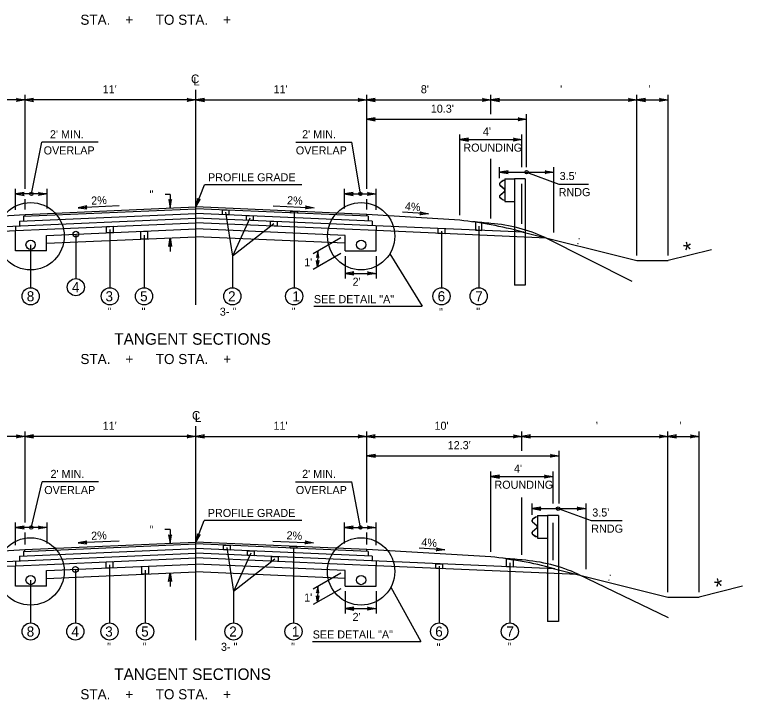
# Model space of a CAD drawing. Extents: x -540 to 1231, y -564 to 421.
# Drawn here: x -30 to 96.3, y 58.8 to 177.6 of the extents above; entities that cross this region are included whole.
import ezdxf

# ---------------------------------------------------------------- set-up
doc = ezdxf.new("R2010")
doc.units = 0
doc.layers.add('1', color=7, linetype='Continuous')
doc.layers.add('Des_ Drain_ Ftrs', color=7, linetype='Continuous')

msp = doc.modelspace()

# ---------------------------------------------------------------- linework, layer by layer
at = {"layer": '1'}
for p, q in [((1.44, 127.24), (1.44, 164.55)), ((-28.2, 147.36), (-28.2, 163.67)), ((31.07, 147.36), (31.07, 163.67)), ((52.63, 160.3), (52.63, 163.67)), ((77.95, 135.79), (77.95, 163.67)), ((83.34, 135.79), (83.34, 163.67)), ((-28.2, 162.79), (-49.75, 162.79)), ((1.44, 162.79), (-28.2, 162.79)), ((1.44, 162.79), (31.07, 162.79)), ((31.07, 162.79), (52.63, 162.79)), ((52.63, 162.79), (77.95, 162.79)), ((77.95, 162.79), (83.34, 162.79)), ((31.07, 159.42), (58.82, 159.42)), ((58.82, 151.14), (58.82, 160.3)), ((47.24, 142.79), (47.24, 156.79)), ((58.01, 151.14), (58.01, 156.79)), ((-27.1, 146.48), (-25.3, 155.43)), ((-15.54, 155.43), (-25.3, 155.43)), ((18.75, 155.43), (28.51, 155.43)), ((29.97, 146.48), (28.51, 155.43)), ((47.24, 155.91), (58.01, 155.91)), ((52.63, 142.23), (52.63, 152.58)), ((54.13, 149.19), (54.13, 151.14)), ((54.13, 150.26), (63.51, 150.26)), ((58.82, 150.26), (64.38, 148.19)), ((63.51, 139.78), (63.51, 151.14)), ((55.04, 149.08), (55.04, 145.15)), ((55.04, 149.08), (56.73, 149.08)), ((56.73, 149.08), (56.73, 130.68)), ((58.55, 149.08), (56.73, 149.08)), ((58.55, 149.08), (58.55, 130.68)), ((1.44, 144.22), (2.92, 148.08)), ((19.84, 148.08), (2.92, 148.08)), ((54.2, 147.97), (54.93, 147.34)), ((54.73, 148.79), (54.21, 148.41)), ((54.22, 148), (54.95, 147.36)), ((54.74, 148.77), (54.23, 148.38)), ((55.04, 148.85), (54.73, 148.79)), ((55.04, 148.82), (54.74, 148.77)), ((58.01, 141.27), (58.01, 148.22)), ((64.38, 148.19), (69.53, 148.19)), ((-29.84, 143.7), (-29.84, 147.36)), ((-24.35, 146.48), (-29.84, 146.48)), ((-24.35, 143.97), (-24.35, 147.36)), ((27.23, 143.97), (27.23, 147.36)), ((27.23, 146.48), (32.71, 146.48)), ((32.71, 143.7), (32.71, 147.36)), ((54.93, 146.89), (54.2, 146.25)), ((54.95, 146.86), (54.22, 146.23)), ((55.01, 147.15), (55.01, 147.07)), ((55.04, 147.15), (55.04, 147.07)), ((-28.2, 143.8), (-28.2, 145.6)), ((-3.02, 146.39), (-3.9, 146.39)), ((-3.02, 146.39), (-3.02, 144.02)), ((31.07, 143.8), (31.07, 145.6)), ((54.21, 145.82), (54.73, 145.43)), ((54.23, 145.84), (54.74, 145.46)), ((54.73, 145.43), (55.04, 145.37)), ((54.74, 145.46), (55.04, 145.4)), ((-28.2, 142.92), (1.44, 144.22)), ((-11.88, 144.4), (-18.97, 144.09)), ((31.08, 142.92), (1.44, 144.22)), ((14.87, 144.39), (21.95, 144.08)), ((55.04, 145.15), (56.73, 145.15)), ((-44.35, 141.91), (-28.2, 142.92)), ((-29.14, 141.77), (1.44, 143.11)), ((-28.44, 142.61), (1.44, 143.92)), ((-28.2, 142.62), (-28.2, 142.92)), ((31.31, 142.61), (1.44, 143.92)), ((32.02, 141.77), (1.44, 143.11)), ((6.6, 143.29), (7.77, 135.66)), ((18.48, 143.31), (18.48, 130.21)), ((31.08, 142.62), (31.08, 142.92)), ((47.24, 141.91), (31.08, 142.92)), ((41.79, 143.01), (37.3, 143.29)), ((-55.46, 139.82), (1.44, 142.3)), ((-29.14, 141.75), (-29.14, 140.97)), ((-28.44, 142.6), (-28.44, 141.8)), ((-24.36, 140.36), (1.44, 141.49)), ((58.35, 139.82), (1.44, 142.3)), ((27.23, 140.36), (1.44, 141.49)), ((10.78, 142.3), (7.77, 135.66)), ((31.31, 142.61), (31.31, 141.8)), ((32.02, 141.77), (32.02, 140.96)), ((-29.85, 140.94), (-29.85, 140.13)), ((-29.85, 140.13), (-24.36, 140.36)), ((-24.46, 139.28), (1.44, 140.41)), ((-13.48, 140.3), (-13.48, 130.21)), ((27.33, 139.28), (1.44, 140.41)), ((14.96, 141.29), (7.77, 135.66)), ((32.72, 140.13), (27.23, 140.36)), ((32.72, 140.93), (32.72, 140.13)), ((50.5, 140.86), (50.5, 130.21)), ((54.13, 141.13), (54.13, 141.13)), ((-59.39, 138.83), (-29.85, 140.13)), ((-29.85, 136.59), (-29.85, 140.13)), ((-24.46, 136.59), (-24.46, 139.28)), ((-24.46, 137.93), (1.44, 139.06)), ((-19.39, 139.5), (-19.39, 131.79)), ((-7.55, 139.35), (-7.55, 130.21)), ((27.33, 137.93), (1.44, 139.06)), ((27.33, 136.59), (27.33, 139.28)), ((27.33, 139.28), (27.33, 139.28)), ((32.72, 136.59), (32.72, 140.13)), ((62.27, 138.83), (32.72, 140.13)), ((44.04, 140.04), (44.04, 130.21)), ((58.01, 139.9), (77.95, 134.91)), ((62.01, 138.9), (77.07, 131.37)), ((-27.23, 137.66), (-27.23, 130.21)), ((-3.02, 138.87), (-3.02, 136.5)), ((26.57, 138.84), (21.81, 136.09)), ((-24.46, 136.59), (-29.85, 136.59)), ((22.57, 136.53), (22.55, 133.83)), ((27.33, 136.59), (32.72, 136.59)), ((90.88, 136.8), (83.34, 134.91)), ((90.88, 136.8), (83.34, 134.91)), ((7.77, 135.66), (7.77, 130.21)), ((26.57, 136.15), (21.8, 133.39)), ((27.33, 135.71), (27.33, 131.82)), ((32.72, 135.71), (32.72, 131.82)), ((35.09, 136.1), (40.68, 127.02)), ((77.95, 134.91), (83.34, 134.91)), ((27.33, 132.7), (32.72, 132.7)), ((58.55, 130.68), (56.73, 130.68)), ((21.9, 127.02), (40.68, 127.02)), ((1.43, 69.09), (1.43, 106.18)), ((-28.2, 89.51), (-28.2, 105.3)), ((31.07, 89.51), (31.07, 105.3)), ((58.01, 101.93), (58.01, 105.3)), ((83.33, 77.41), (83.33, 105.3)), ((88.72, 77.41), (88.72, 105.3)), ((-28.2, 104.42), (-55.14, 104.42)), ((1.43, 104.42), (-28.2, 104.42)), ((1.43, 104.42), (31.07, 104.42)), ((31.07, 104.42), (58.01, 104.42)), ((58.01, 104.42), (83.33, 104.42)), ((83.33, 104.42), (88.72, 104.42)), ((31.08, 101.05), (64.45, 101.05)), ((64.45, 92.78), (64.45, 101.93)), ((52.62, 84.41), (52.62, 98.32)), ((52.62, 97.44), (63.4, 97.44)), ((63.4, 92.78), (63.4, 98.32)), ((-27.08, 88.74), (-25.21, 96.52)), ((-15.44, 96.52), (-25.21, 96.52)), ((18.74, 96.52), (28.51, 96.52)), ((29.97, 88.63), (28.51, 96.52)), ((58.01, 83.87), (58.01, 93.8)), ((59.75, 90.82), (59.75, 92.78)), ((69.14, 81.41), (69.14, 92.78)), ((59.75, 91.9), (69.14, 91.9)), ((64.27, 91.9), (70.03, 89.82)), ((1.43, 86.07), (2.89, 89.85)), ((19.81, 89.85), (2.89, 89.85)), ((60.37, 90.43), (59.84, 90.04)), ((60.39, 90.4), (59.86, 90.01)), ((60.7, 90.48), (60.37, 90.43)), ((60.7, 90.45), (60.39, 90.4)), ((60.7, 90.71), (60.7, 86.78)), ((60.7, 90.71), (62.45, 90.71)), ((62.45, 90.71), (62.45, 72.31)), ((64.34, 90.71), (62.45, 90.71)), ((64.34, 90.71), (64.34, 72.31)), ((70.03, 89.82), (75.38, 89.82)), ((-24.38, 88.63), (-29.86, 88.63)), ((-29.84, 85.56), (-29.84, 89.51)), ((-24.36, 85.83), (-24.36, 89.51)), ((27.23, 85.83), (27.23, 89.51)), ((27.23, 88.63), (32.71, 88.63)), ((32.71, 85.56), (32.71, 89.51)), ((59.82, 89.61), (60.58, 88.97)), ((60.58, 88.52), (59.82, 87.88)), ((59.84, 89.63), (60.6, 88.99)), ((60.6, 88.5), (59.84, 87.86)), ((60.67, 88.78), (60.67, 88.71)), ((60.7, 88.78), (60.7, 88.71)), ((63.4, 82.95), (63.4, 89.42)), ((-28.2, 85.66), (-28.2, 87.75)), ((-3.05, 88.25), (-3.93, 88.25)), ((-3.05, 88.25), (-3.05, 85.88)), ((31.07, 85.66), (31.07, 87.75)), ((59.84, 87.45), (60.37, 87.06)), ((59.86, 87.48), (60.39, 87.09)), ((-28.21, 84.78), (1.43, 86.07)), ((-11.89, 86.27), (-18.97, 85.96)), ((31.07, 84.78), (1.43, 86.07)), ((14.78, 86.27), (21.86, 85.96)), ((60.37, 87.06), (60.7, 87.01)), ((60.39, 87.09), (60.7, 87.04)), ((60.7, 86.78), (62.45, 86.78)), ((-49.74, 83.53), (-28.21, 84.78)), ((-29.15, 83.63), (1.43, 84.96)), ((-28.44, 84.47), (1.43, 85.77)), ((-28.21, 84.48), (-28.21, 84.78)), ((31.31, 84.47), (1.43, 85.77)), ((32.02, 83.63), (1.43, 84.96)), ((6.81, 85.13), (7.97, 77.51)), ((18.38, 85.18), (18.38, 72.06)), ((31.07, 84.48), (31.07, 84.78)), ((52.62, 83.53), (31.07, 84.78)), ((44.64, 84.74), (40.15, 85.01)), ((-60.85, 81.44), (1.43, 84.16)), ((-29.14, 83.63), (-29.14, 82.82)), ((-28.44, 84.47), (-28.44, 83.66)), ((-24.36, 82.22), (1.43, 83.35)), ((63.72, 81.44), (1.43, 84.16)), ((27.23, 82.22), (1.43, 83.35)), ((10.98, 84.15), (7.97, 77.51)), ((31.31, 84.47), (31.31, 83.65)), ((32.02, 83.63), (32.02, 82.82)), ((-29.85, 82.79), (-29.85, 81.98)), ((-29.85, 81.98), (-24.36, 82.22)), ((-24.46, 81.14), (1.43, 82.27)), ((-13.54, 82.15), (-13.54, 72.06)), ((27.33, 81.14), (1.43, 82.27)), ((15.16, 83.14), (7.97, 77.51)), ((32.72, 81.98), (27.23, 82.22)), ((32.72, 82.79), (32.72, 81.98)), ((55.9, 82.47), (55.9, 72.06)), ((59.75, 82.76), (59.75, 82.76)), ((-64.78, 80.46), (-29.85, 81.98)), ((-29.85, 78.44), (-29.85, 81.98)), ((-24.46, 78.44), (-24.46, 81.14)), ((-24.46, 79.79), (1.43, 80.92)), ((-19.47, 81.35), (-19.47, 72.06)), ((-7.36, 81.21), (-7.36, 72.06)), ((27.33, 79.79), (1.43, 80.92)), ((27.33, 78.44), (27.33, 81.14)), ((27.33, 81.14), (27.33, 81.14)), ((32.72, 78.44), (32.72, 81.98)), ((67.65, 80.45), (32.72, 81.98)), ((32.72, 81.83), (32.72, 81.83)), ((43.63, 81.91), (43.63, 72.06)), ((63.4, 81.52), (83.33, 76.53)), ((-3.05, 80.73), (-3.05, 78.36)), ((26.57, 80.7), (21.81, 77.95)), ((67.76, 80.53), (83.37, 73.01)), ((-24.46, 78.44), (-29.85, 78.44)), ((-27.23, 79.51), (-27.23, 72.06)), ((22.57, 78.39), (22.55, 75.68)), ((27.33, 78.44), (32.72, 78.44)), ((35.28, 78.3), (40.48, 68.87)), ((96.25, 78.42), (88.72, 76.53)), ((7.97, 77.51), (7.97, 72.06)), ((26.57, 78), (21.79, 75.25)), ((27.33, 77.56), (27.33, 73.68)), ((32.72, 77.56), (32.72, 73.68)), ((83.33, 76.53), (88.72, 76.53)), ((27.33, 74.56), (32.72, 74.56)), ((64.34, 72.31), (62.45, 72.31)), ((21.69, 68.87), (40.48, 68.87))]:
    msp.add_line(p, q, dxfattribs=at)
for points in [[(6.03, 143.72), (7.18, 143.67), (7.18, 142.86), (6.03, 142.91)], [(10.21, 142.73), (11.35, 142.68), (11.35, 141.87), (10.21, 141.92)], [(17.91, 143.5), (19.06, 143.45), (19.06, 143.15), (17.91, 143.2)], [(14.38, 141.73), (15.53, 141.68), (15.53, 140.88), (14.38, 140.93)], [(51.05, 140.14), (51.05, 141.46), (49.96, 141.63), (49.96, 140.19)], [(-14.06, 140.81), (-12.91, 140.86), (-12.91, 139.79), (-14.06, 139.74)], [(44.68, 139.6), (44.68, 140.41), (43.4, 140.47), (43.4, 139.66)], [(-8.13, 139.99), (-6.98, 140.04), (-6.98, 138.7), (-8.13, 138.65)], [(6.23, 85.56), (7.38, 85.51), (7.38, 84.71), (6.23, 84.76)], [(17.81, 85.36), (18.95, 85.31), (18.95, 85.01), (17.81, 85.06)], [(10.41, 84.57), (11.56, 84.52), (11.56, 83.71), (10.41, 83.76)], [(14.58, 83.58), (15.73, 83.53), (15.73, 82.72), (14.58, 82.77)], [(-14.11, 82.67), (-12.97, 82.72), (-12.97, 81.64), (-14.11, 81.59)], [(43.05, 82.34), (44.2, 82.29), (44.2, 81.48), (43.05, 81.53)], [(55.33, 83.19), (56.48, 83.02), (56.48, 81.75), (55.33, 81.8)], [(-7.93, 81.86), (-6.78, 81.91), (-6.78, 80.56), (-7.93, 80.51)]]:
    msp.add_lwpolyline(points, close=True, dxfattribs=at)
for centre, radius in [((58.82, 150.26), 0.3), ((-27.1, 146.48), 0.3), ((29.97, 146.48), 0.3), ((-27.23, 139.15), 5.84), ((30.11, 139.15), 5.84), ((-19.39, 139.5), 0.5), ((-27.23, 137.66), 0.808), ((30.11, 137.66), 0.808), ((-19.39, 130.3), 1.49), ((-27.23, 128.72), 1.49), ((-13.48, 128.72), 1.49), ((-7.55, 128.72), 1.49), ((7.77, 128.72), 1.49), ((18.48, 128.72), 1.49), ((44.04, 128.72), 1.49), ((50.5, 128.72), 1.49), ((-27.12, 88.63), 0.3), ((29.97, 88.63), 0.3), ((-27.24, 81), 5.84), ((30.1, 81), 5.84), ((-19.47, 81.35), 0.5), ((-27.23, 79.51), 0.808), ((30.1, 79.51), 0.808), ((-27.23, 70.58), 1.49), ((-19.47, 70.58), 1.49), ((-13.54, 70.58), 1.49), ((-7.36, 70.58), 1.49), ((7.97, 70.58), 1.49), ((18.38, 70.58), 1.49), ((43.63, 70.58), 1.49), ((55.9, 70.58), 1.49)]:
    msp.add_circle(centre, radius, dxfattribs=at)
for centre, radius, start, end in [((54.38, 148.18), 0.278, 126.9799, 229.021), ((54.38, 148.18), 0.249, 126.9799, 229.021), ((54.77, 147.15), 0.249, 0, 49.0365), ((54.77, 147.07), 0.249, 310.9635, 0), ((54.77, 147.15), 0.278, 0, 49.0365), ((54.77, 147.07), 0.278, 310.9635, 0), ((54.38, 146.04), 0.278, 130.979, 233.0201), ((54.38, 146.04), 0.249, 130.979, 233.0201), ((40.35, 75.07), 67.19, 74.7619, 84.1205), ((41.81, 40.69), 101.24, 83.8633, 85.6775), ((50.51, 114.07), 27.37, 65.1374, 85.5513), ((45.74, 16.69), 67.19, 74.7598, 84.1183)]:
    msp.add_arc(centre, radius, start, end, dxfattribs=at)
msp.add_ellipse((64.27, 91.89), major_axis=(-0.311, 0), ratio=0.964041, dxfattribs=at)
for centre, major_axis, start_param, end_param in [((60.01, 89.82), (-0.288, 0), 5.35781, 7.138763), ((60.01, 89.82), (-0.258, 0), 5.35781, 7.138763), ((60.41, 88.78), (0.258, 0), 0, 0.855848), ((60.41, 88.71), (0.258, 0), 5.427337, 6.283185), ((60.41, 88.78), (0.288, 0), 0, 0.855848), ((60.41, 88.71), (0.288, 0), 5.427337, 6.283185), ((60.01, 87.67), (-0.288, 0), 5.427608, 7.208561), ((60.01, 87.67), (-0.258, 0), 5.427608, 7.208561), ((46.8, -17.68), (105.02, 0), 1.463691, 1.495354), ((55.82, 55.7), (28.39, 0), 1.136862, 1.493152)]:
    msp.add_ellipse(centre, major_axis=major_axis, ratio=0.964041, start_param=start_param, end_param=end_param, dxfattribs=at)
at = {"layer": 'Des_ Drain_ Ftrs'}
for points in [[(-28.2, 162.79), (-29.69, 162.54), (-29.39, 162.79), (-29.69, 163.03)], [(-28.2, 162.79), (-26.71, 162.54), (-27.01, 162.79), (-26.71, 163.03)], [(1.44, 162.79), (-0.05, 162.54), (0.24, 162.79), (-0.05, 163.03)], [(1.44, 162.79), (2.93, 162.54), (2.63, 162.79), (2.93, 163.03)], [(31.07, 162.79), (29.58, 162.54), (29.88, 162.79), (29.58, 163.03)], [(31.07, 162.79), (32.56, 162.54), (32.27, 162.79), (32.56, 163.03)], [(52.63, 162.79), (51.14, 162.54), (51.43, 162.79), (51.14, 163.03)], [(52.63, 162.79), (54.11, 162.54), (53.82, 162.79), (54.11, 163.03)], [(77.95, 162.79), (76.47, 162.54), (76.76, 162.79), (76.47, 163.03)], [(77.95, 162.79), (79.44, 162.54), (79.15, 162.79), (79.44, 163.03)], [(83.34, 162.79), (81.85, 162.54), (82.15, 162.79), (81.85, 163.03)], [(31.07, 159.42), (32.56, 159.17), (32.27, 159.42), (32.56, 159.67)], [(58.82, 159.42), (57.33, 159.17), (57.63, 159.42), (57.33, 159.67)], [(47.24, 155.91), (48.72, 155.66), (48.43, 155.91), (48.72, 156.16)], [(58.01, 155.91), (56.52, 155.66), (56.82, 155.91), (56.52, 156.16)], [(54.13, 150.26), (55.62, 150.01), (55.32, 150.26), (55.62, 150.51)], [(63.51, 150.26), (62.03, 150.01), (62.32, 150.26), (62.03, 150.51)], [(-29.84, 146.48), (-28.35, 146.23), (-28.65, 146.48), (-28.35, 146.73)], [(-24.35, 146.48), (-25.84, 146.23), (-25.55, 146.48), (-25.84, 146.73)], [(27.23, 146.48), (28.72, 146.23), (28.42, 146.48), (28.72, 146.73)], [(32.71, 146.48), (31.23, 146.23), (31.52, 146.48), (31.23, 146.73)], [(-3.02, 144.02), (-2.78, 145.51), (-3.02, 145.22), (-3.27, 145.51)], [(1.44, 144.22), (2.2, 145.52), (1.86, 145.33), (1.74, 145.7)], [(-18.97, 144.09), (-17.47, 143.91), (-17.77, 144.14), (-17.49, 144.41)], [(21.95, 144.08), (20.45, 143.89), (20.76, 144.13), (20.48, 144.39)], [(41.79, 143.01), (40.29, 142.85), (40.59, 143.08), (40.32, 143.35)], [(-3.02, 138.87), (-2.78, 137.38), (-3.02, 137.68), (-3.27, 137.38)], [(22.57, 136.53), (22.38, 135.45), (22.57, 135.66), (22.75, 135.45)], [(22.55, 133.83), (22.38, 134.91), (22.56, 134.7), (22.74, 134.91)], [(27.33, 132.7), (28.82, 132.45), (28.52, 132.7), (28.82, 132.95)], [(32.72, 132.7), (31.23, 132.45), (31.53, 132.7), (31.23, 132.95)], [(-28.2, 104.42), (-29.69, 104.17), (-29.39, 104.42), (-29.69, 104.67)], [(-28.2, 104.42), (-26.71, 104.17), (-27.01, 104.42), (-26.71, 104.67)], [(1.43, 104.42), (-0.05, 104.17), (0.24, 104.42), (-0.05, 104.67)], [(1.43, 104.42), (2.92, 104.17), (2.63, 104.42), (2.92, 104.67)], [(31.07, 104.42), (29.58, 104.17), (29.88, 104.42), (29.58, 104.67)], [(31.07, 104.42), (32.56, 104.17), (32.26, 104.42), (32.56, 104.67)], [(58.01, 104.42), (56.52, 104.17), (56.82, 104.42), (56.52, 104.67)], [(58.01, 104.42), (59.5, 104.17), (59.2, 104.42), (59.5, 104.67)], [(83.33, 104.42), (81.84, 104.17), (82.14, 104.42), (81.84, 104.67)], [(83.33, 104.42), (84.82, 104.17), (84.52, 104.42), (84.82, 104.67)], [(88.72, 104.42), (87.23, 104.17), (87.52, 104.42), (87.23, 104.67)], [(31.08, 101.05), (32.57, 100.8), (32.27, 101.05), (32.57, 101.3)], [(64.45, 101.05), (62.96, 100.8), (63.25, 101.05), (62.96, 101.3)], [(52.62, 97.44), (54.11, 97.2), (53.81, 97.44), (54.11, 97.69)], [(63.4, 97.44), (61.91, 97.2), (62.2, 97.44), (61.91, 97.69)], [(59.75, 91.9), (61.3, 91.65), (60.99, 91.9), (61.3, 92.14)], [(69.14, 91.9), (67.59, 91.65), (67.9, 91.9), (67.59, 92.14)], [(-29.86, 88.63), (-28.38, 88.38), (-28.67, 88.63), (-28.38, 88.88)], [(-24.38, 88.63), (-25.87, 88.38), (-25.57, 88.63), (-25.87, 88.88)], [(27.23, 88.63), (28.71, 88.38), (28.42, 88.63), (28.71, 88.88)], [(32.71, 88.63), (31.22, 88.38), (31.52, 88.63), (31.22, 88.88)], [(-3.05, 85.88), (-2.8, 87.37), (-3.05, 87.07), (-3.29, 87.37)], [(1.43, 86.07), (2.2, 87.37), (1.86, 87.19), (1.74, 87.55)], [(-18.97, 85.96), (-17.48, 85.77), (-17.78, 86.01), (-17.5, 86.27)], [(21.86, 85.96), (20.36, 85.78), (20.67, 86.01), (20.38, 86.28)], [(44.64, 84.74), (43.14, 84.58), (43.45, 84.81), (43.17, 85.08)], [(-3.05, 80.73), (-2.8, 79.24), (-3.05, 79.53), (-3.29, 79.24)], [(22.57, 78.39), (22.38, 77.31), (22.56, 77.52), (22.74, 77.3)], [(22.55, 75.68), (22.38, 76.77), (22.56, 76.55), (22.74, 76.77)], [(27.33, 74.56), (28.82, 74.31), (28.52, 74.56), (28.82, 74.8)], [(32.72, 74.56), (31.23, 74.31), (31.52, 74.56), (31.23, 74.8)]]:
    msp.add_lwpolyline(points, close=True, dxfattribs=at)

# ---------------------------------------------------------------- texts
at = {"layer": '1'}
for s, height, p in [('STA.    +      TO STA.    +     ', 1.75, (-18.6, 175.82)), ("11'", 1.4, (-14.73, 163.94)), ("11'", 1.4, (14.91, 163.94)), ("8'", 1.4, (40.46, 163.94)), ("  '", 1.4, (63.59, 163.94)), (" '", 1.4, (79.45, 163.94)), ("10.3'", 1.4, (42.19, 160.57)), ("4'", 1.4, (51.23, 156.61)), ("2' MIN.", 1.4, (-23.88, 156.13)), ("2' MIN.", 1.4, (19.87, 156.13)), ('OVERLAP', 1.4, (-24.97, 153.33)), ('OVERLAP', 1.4, (18.78, 153.33)), ('ROUNDING', 1.4, (47.84, 153.81)), ("3.5'", 1.4, (64.54, 148.89)), ('PROFILE GRADE', 1.4, (3.54, 148.66)), ('RNDG', 1.4, (64.37, 146.09)), ("2'", 1.4, (28.62, 130.55)), ('4', 1.75, (-20.06, 129.43)), ('8', 1.75, (-27.9, 127.85)), ('3', 1.75, (-14.24, 127.85)), ('5', 1.75, (-8.24, 127.85)), ('2', 1.75, (7.02, 127.85)), ('1', 1.75, (18.18, 127.85)), ('SEE DETAIL "A"', 1.4, (21.91, 127.53)), ('6', 1.75, (43.38, 127.85)), ('7', 1.75, (49.91, 127.85)), (' "', 1.4, (-14.43, 125.36)), (' "', 1.4, (-8.5, 125.36)), ('3- "', 1.4, (5.59, 125.36)), (' "', 1.4, (17.54, 125.36)), (' "', 1.4, (43.1, 125.27)), (' "', 1.4, (49.55, 125.36)), ('TANGENT SECTIONS', 2, (-12.74, 120.32)), ('STA.    +      TO STA.    +     ', 1.75, (-18.59, 116.97)), ("11'", 1.4, (-14.73, 105.57)), ("11'", 1.4, (14.9, 105.57)), ("10'", 1.4, (42.83, 105.57)), ("  '", 1.4, (69.79, 105.57)), (" '", 1.4, (84.83, 105.57)), ("12.3'", 1.4, (45.12, 102.2)), ("2' MIN.", 1.4, (-23.78, 97.22)), ("2' MIN.", 1.4, (19.87, 97.22)), ("4'", 1.4, (56.62, 98.14)), ('ROUNDING', 1.4, (53.23, 95.34)), ('OVERLAP', 1.4, (-24.87, 94.42)), ('OVERLAP', 1.4, (18.78, 94.42)), ('PROFILE GRADE', 1.4, (3.5, 90.44)), ("3.5'", 1.4, (70.2, 90.52)), ('RNDG', 1.4, (70.02, 87.72)), ("2'", 1.4, (28.62, 72.41)), ('8', 1.75, (-27.91, 69.7)), ('4', 1.75, (-20.15, 69.7)), ('3', 1.75, (-14.29, 69.7)), ('5', 1.75, (-8.05, 69.7)), ('2', 1.75, (7.22, 69.7)), ('1', 1.75, (18.08, 69.7)), ('SEE DETAIL "A"', 1.4, (21.7, 69.37)), ('6', 1.75, (42.96, 69.7)), ('7', 1.75, (55.31, 69.7)), (' "', 1.4, (-14.48, 67.22)), (' "', 1.4, (-8.3, 67.22)), ('3- "', 1.4, (5.79, 67.22)), (' "', 1.4, (17.44, 67.22)), (' "', 1.4, (42.68, 67.12)), (' "', 1.4, (54.96, 67.22)), ('TANGENT SECTIONS', 2, (-12.74, 62.18)), ('STA.    +      TO STA.    +     ', 1.75, (-18.6, 58.82))]:
    msp.add_text(s, height=height, dxfattribs=at).set_placement(p)
for s, height, rotation, p in [('  "', 1.4, 0.1438, (-7.64, 145.69)), ('2%', 1.4, 2.6268, (-16.69, 144.61)), ('2%', 1.4, 357.3731, (17.23, 144.7)), ('4%', 1.4, 356.1259, (37.66, 143.66)), (' : ', 1.4, 345.7718, (66.93, 137.96)), ('*', 2.8, 12.8479, (86.43, 135.27)), ("1'", 1.4, 0.1438, (20.23, 133.92)), ('  "', 1.4, 0.1438, (-7.66, 87.54)), ('2%', 1.4, 2.6267, (-16.7, 86.47)), ('2%', 1.4, 357.3732, (17.14, 86.59)), ('4%', 1.4, 356.3899, (40.51, 85.38)), (' : ', 1.4, 345.7718, (72.31, 79.58)), ('*', 2.8, 12.8479, (91.81, 76.89)), ("1'", 1.4, 0.1438, (20.22, 75.77))]:
    msp.add_text(s, height=height, rotation=rotation, dxfattribs=at).set_placement(p)
at = {"layer": 'Des_ Drain_ Ftrs'}
for s, p in [('C', (0.59, 165.69)), ('L', (0.98, 165.29)), ('C', (0.76, 107.31)), ('L', (1.26, 106.92))]:
    msp.add_text(s, height=1.5, dxfattribs=at).set_placement(p)

doc.saveas('drawing.dxf')
